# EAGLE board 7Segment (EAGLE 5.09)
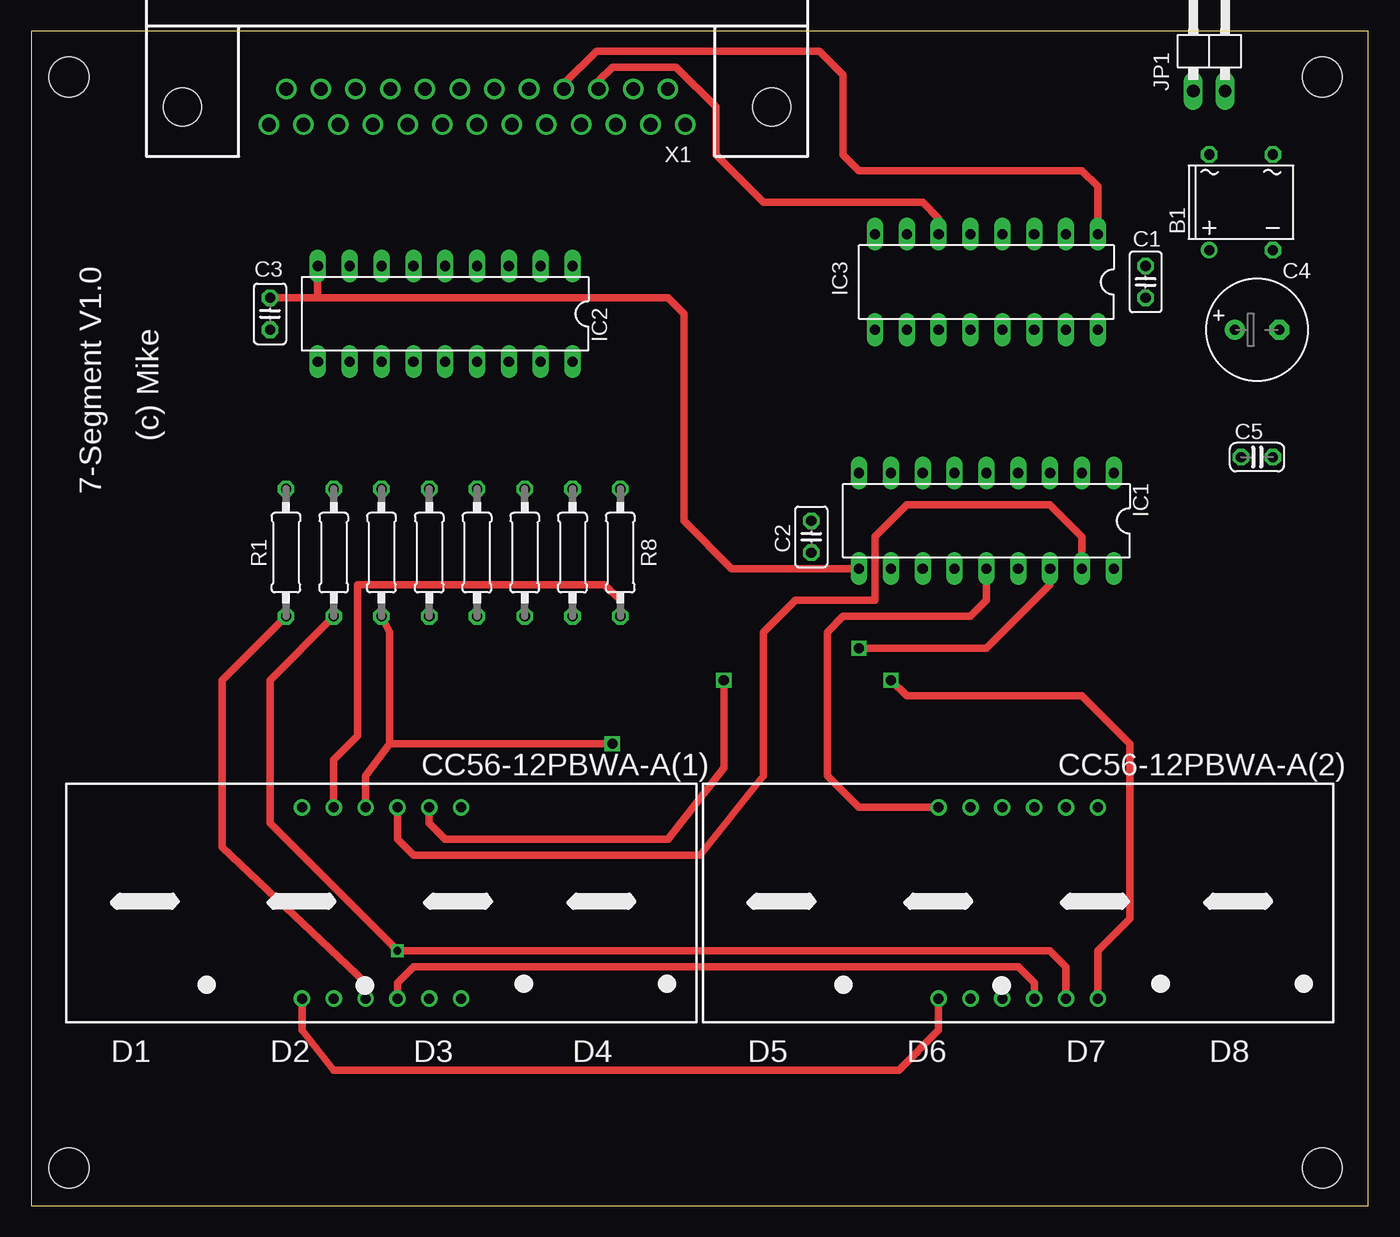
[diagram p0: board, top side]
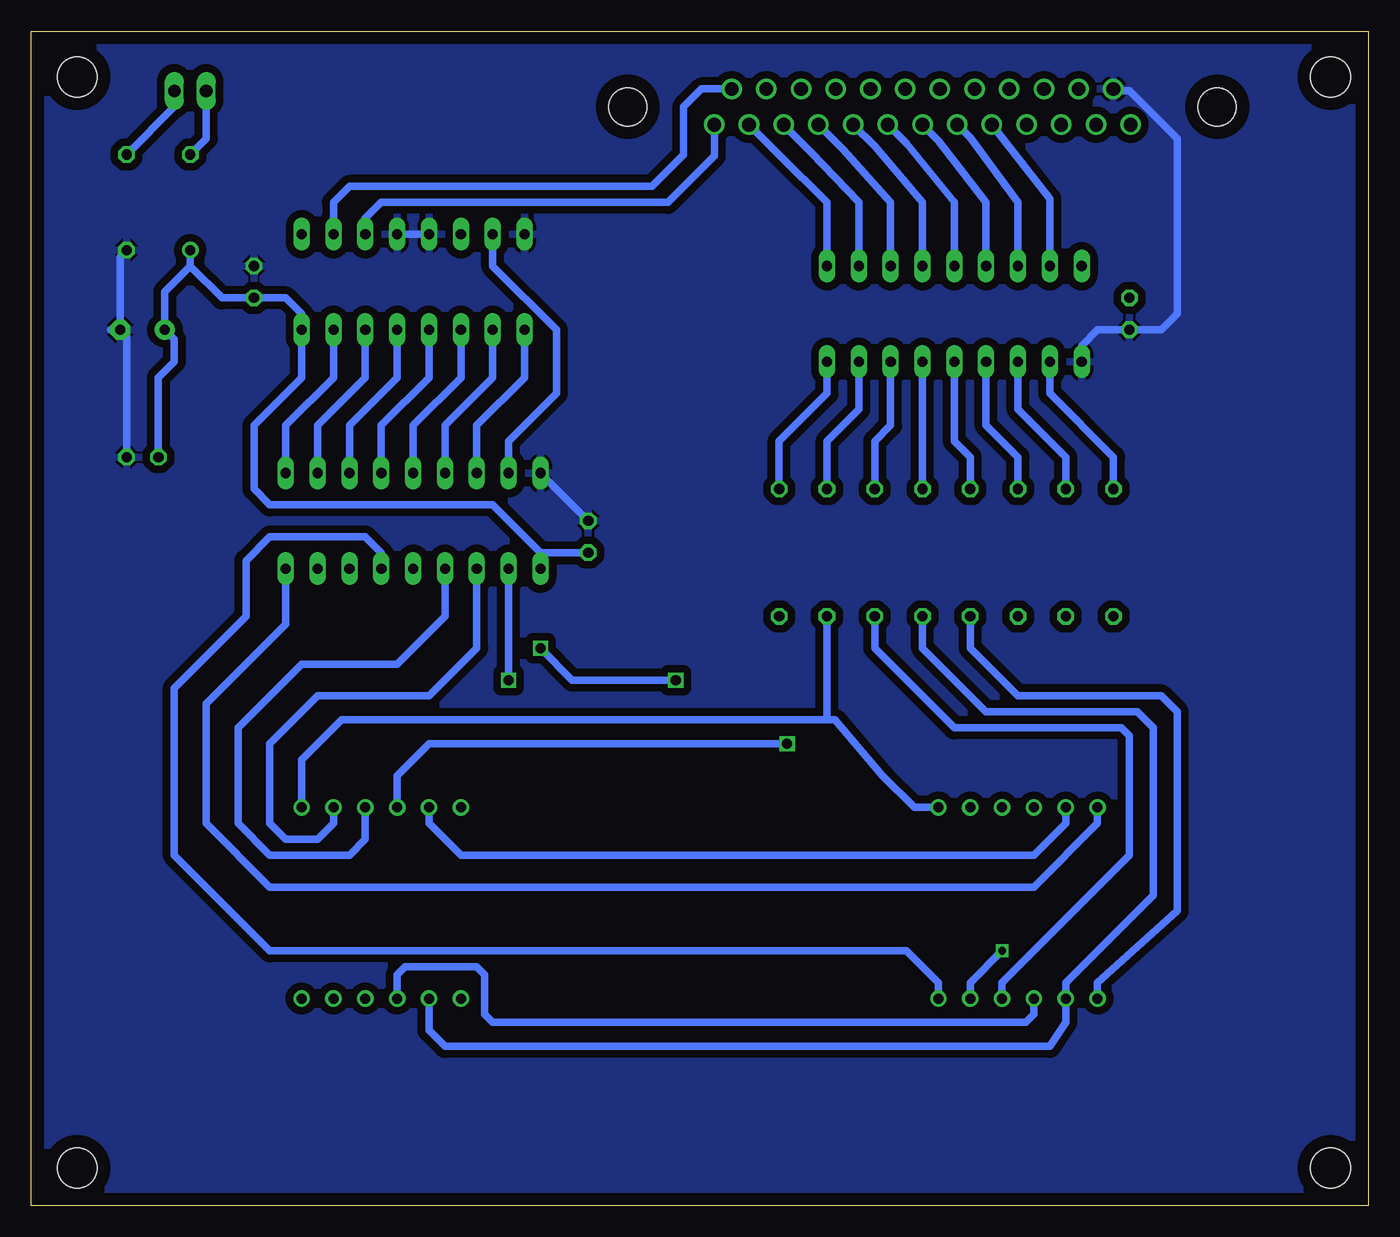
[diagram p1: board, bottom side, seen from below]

Size 106.66 x 93.65 mm. Coordinates in mm from the lower left corner, seen from the top.
Outline: 0,0 106.66,0 106.66,93.65 0,93.65 0,0
Copper layers (1*16): Top 0.035mm / dielectric 1.5mm / Bottom 0.035mm
Design rules "Bilex DRU": minimum track width 10mil, minimum drill 24mil, track to track 10mil, track to pad 10mil, pad to pad 10mil, via to via 10mil, smd to smd 10mil, copper to edge 40mil, drill to drill 8mil, minimum pad ring 10mil, minimum via ring 8mil, stop-mask expansion 4mil, vias tented up to drill 0mil, thermal gap 10mil
Holes 3.2 mm at 3,90 103,90 103,3 3,3

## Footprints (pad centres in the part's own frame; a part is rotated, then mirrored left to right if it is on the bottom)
DB = drill 0.813 round: + -2.54,-3.81 | drill 0.813 octagon: - 2.54,-3.81; AC1 2.54,3.81; AC2 -2.54,3.81
C025-025X050 = drill 0.813 octagon: 1 -1.27,0; 2 1.27,0
E3,5-8 = drill 0.813 pad 1.6 round: + -1.778,0 | drill 0.813 pad 1.6 octagon: - 1.778,0
C025-024X044 = drill 0.813 octagon: 1 -1.27,0; 2 1.27,0
4-FACH-7-SEG = drill 0.8 round: P1 -6.35,-7.62; P2 -3.81,-7.62; P3 -1.27,-7.62; P4 1.27,-7.62; P5 3.81,-7.62; P6 6.35,-7.62; P7 6.35,7.62; P8 3.81,7.62; P9 1.27,7.62; P10 -1.27,7.62; P11 -3.81,7.62; P12 -6.35,7.62
DIL18 = drill 0.813 long: 1 -10.16,-3.81; 2 -7.62,-3.81; 3 -5.08,-3.81; 4 -2.54,-3.81; 5 0,-3.81; 6 2.54,-3.81; 7 5.08,-3.81; 8 7.62,-3.81; 9 10.16,-3.81; 10 10.16,3.81; 11 7.62,3.81; 12 5.08,3.81; 13 2.54,3.81; 14 0,3.81; 15 -2.54,3.81; 16 -5.08,3.81; 17 -7.62,3.81; 18 -10.16,3.81
DIL16 = drill 0.813 long: 1 -8.89,-3.81; 2 -6.35,-3.81; 3 -3.81,-3.81; 4 -1.27,-3.81; 5 1.27,-3.81; 6 3.81,-3.81; 7 6.35,-3.81; 8 8.89,-3.81; 9 8.89,3.81; 10 6.35,3.81; 11 3.81,3.81; 12 1.27,3.81; 13 -1.27,3.81; 14 -3.81,3.81; 15 -6.35,3.81; 16 -8.89,3.81
1X02/90 = drill 1.016 long: 1 -1.27,-3.81; 2 1.27,-3.81
0207/10 = drill 0.813 octagon: 1 -5.08,0; 2 5.08,0
H3M25RA = drill 1.092 round: 1 -16.612,1.422; 2 -13.843,1.422; 3 -11.074,1.422; 4 -8.306,1.422; 5 -5.537,1.422; 6 -2.769,1.422; 7 0,1.422; 8 2.769,1.422; 9 5.537,1.422; 10 8.306,1.422; 11 11.074,1.422; 12 13.843,1.422; 13 16.612,1.422; 14 -15.227,-1.422; 15 -12.459,-1.422; 16 -9.69,-1.422; 17 -6.921,-1.422; 18 -4.153,-1.422; 19 -1.384,-1.422; 20 1.384,-1.422; 21 4.153,-1.422; 22 6.921,-1.422; 23 9.69,-1.422; 24 12.459,-1.422; 25 15.227,-1.422 | hole 3.048: -23.52,0; 23.52,0

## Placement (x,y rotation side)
B1  DBDB105G  [DB]  96.52,80.01 0 top
C1  100n  [C025-025X050]  88.9,73.66 270 top
C2  100n  [C025-025X050]  62.23,53.34 90 top
C3  100n  [C025-025X050]  19.05,71.12 90 top
C4  220u  [E3,5-8]  97.79,69.85 0 top
C5  100n  [C025-024X044]  97.79,59.69 0 top
CC56-12PBWA-A(1)  4-FACH-7-SEGCC56-12EWA  [4-FACH-7-SEG]  27.94,24.13 0 top
CC56-12PBWA-A(2)  4-FACH-7-SEGCC56-12EWA  [4-FACH-7-SEG]  78.74,24.13 0 top
IC1  ULN2803  [DIL18]  76.2,54.61 180 top
IC2  UDN2981A  [DIL18]  33.02,71.12 180 top
IC3  74237N  [DIL16]  76.2,73.66 180 top
JP1  [1X02/90]  93.98,92.71 0 top
R1  100  [0207/10]  20.32,52.07 90 top
R2  100  [0207/10]  24.13,52.07 90 top
R3  100  [0207/10]  27.94,52.07 90 top
R4  100  [0207/10]  31.75,52.07 90 top
R5  100  [0207/10]  35.56,52.07 90 top
R6  100  [0207/10]  39.37,52.07 90 top
R7  100  [0207/10]  43.18,52.07 90 top
R8  100  [0207/10]  46.99,52.07 90 top
X1  D-SUB25-H3M25RA  [H3M25RA]  35.56,87.63 180 top

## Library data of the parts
B1 = rectifier
C1-C5 R1-R8 = rcl
CC56-12PBWA-A(1) CC56-12PBWA-A(2) = MikeLib
IC1 IC2 = uln-udn
IC3 = 74ttl-din
JP1 = pinhead
X1 = con-thomas-betts

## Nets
+5V: B1.+ C1.2 C2.1 C3.2 C4.+ C5.1 IC1.10 IC2.9 IC3.16
GND: B1.- C1.1 C2.2 C3.1 C4.- C5.2 IC1.9 IC2.10 IC3.4 IC3.5 IC3.8 X1.25
N$1: IC2.11 R1.2
N$2: IC2.12 R2.2
N$3: IC2.13 R3.2
N$4: IC2.14 R4.2
N$5: IC2.15 R5.2
N$6: IC2.16 R6.2
N$7: IC2.17 R7.2
N$8: IC2.18 R8.2
N$9: IC1.1 IC3.15
N$10: IC1.2 IC3.14
N$11: IC1.3 IC3.13
N$12: IC1.4 IC3.12
N$13: IC1.5 IC3.11
N$14: IC1.6 IC3.10
N$15: IC1.7 IC3.9
N$16: IC1.8 IC3.7
N$17: CC56-12PBWA-A(1).P3 CC56-12PBWA-A(2).P3 R1.1
N$18: CC56-12PBWA-A(1).P5 CC56-12PBWA-A(2).P5 R2.1
N$19: CC56-12PBWA-A(1).P10 CC56-12PBWA-A(2).P10 R3.1
N$20: CC56-12PBWA-A(1).P1 CC56-12PBWA-A(2).P1 R4.1
N$21: CC56-12PBWA-A(1).P2 CC56-12PBWA-A(2).P2 R5.1
N$22: CC56-12PBWA-A(1).P4 CC56-12PBWA-A(2).P4 R6.1
N$23: CC56-12PBWA-A(1).P7 CC56-12PBWA-A(2).P7 R7.1
N$24: CC56-12PBWA-A(1).P11 CC56-12PBWA-A(2).P11 R8.1
N$25: CC56-12PBWA-A(2).P6 IC1.11
N$26: CC56-12PBWA-A(2).P8 IC1.12
N$27: CC56-12PBWA-A(2).P9 IC1.13
N$28: CC56-12PBWA-A(2).P12 IC1.14
N$29: CC56-12PBWA-A(1).P12 IC1.18
N$30: CC56-12PBWA-A(1).P6 IC1.15
N$31: CC56-12PBWA-A(1).P8 IC1.16
N$32: CC56-12PBWA-A(1).P9 IC1.17
N$33: IC2.8 X1.9
N$34: B1.AC1 JP1.2
N$35: IC2.7 X1.8
N$36: IC2.6 X1.7
N$37: IC2.5 X1.6
N$38: IC2.4 X1.5
N$39: IC2.3 X1.4
N$40: IC2.2 X1.3
N$41: IC2.1 X1.2
N$42: B1.AC2 JP1.1
SUB25-D1: IC3.3 X1.1
SUB25-D14: IC3.2 X1.14
SUB25-D16: IC3.6 X1.16
SUB25-D17: IC3.1 X1.17

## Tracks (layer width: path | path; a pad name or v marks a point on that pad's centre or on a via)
+5V
  Top 0.61: C3.2 22.86,72.39 | 22.86,72.39 IC2.9 | 22.86,72.39 50.8,72.39 52.07,71.12 52.07,54.61 55.88,50.8 IC1.10
  Bottom 0.6: C2.1 66.04,52.07 IC1.10 | C1.2 86.36,72.39 85.09,71.12 IC3.16
  Bottom 0.61: 66.04,52.07 69.85,55.88 87.63,55.88 88.9,57.15 88.9,62.23 85.09,66.04 IC3.16 | 93.98,74.93 91.44,72.39 C1.2 | 93.98,74.93 B1.+ | 93.98,74.93 96.01,72.9 C4.+ 95.25,69.09 95.25,67.31 96.52,66.04 C5.1
GND
  Bottom 0.6: C2.2 IC1.9 | IC3.5 IC3.4
  Bottom 0.61: IC2.10 22.86,68.58 21.59,69.85 C3.1 16.51,69.85 15.24,71.12 15.24,85.09 19.05,88.9 20.18,88.9 X1.25 | C5.2 99.06,69.85 C4.- | C4.- 100.33,69.85 | C4.- 99.57,75.69 B1.-
  pour Bottom (isolate 0.61): -7.62,97.79 113.03,97.79 113.03,93.98 114.3,93.98 114.3,-6.35 -6.35,-6.35 -6.35,-5.08 -7.62,-5.08
N$1
  Bottom 0.6: IC2.11 25.4,64.77 20.32,59.69 R1.2
N$2
  Bottom 0.6: IC2.12 27.94,63.5 24.13,59.69 R2.2
N$3
  Bottom 0.6: IC2.13 30.48,62.23 27.94,59.69 R3.2
N$4
  Bottom 0.6: IC2.14 33.02,60.96 31.75,59.69 R4.2
N$5
  Bottom 0.6: R5.2 IC2.15
N$6
  Bottom 0.6: IC2.16 38.1,62.23 39.37,60.96 R6.2
N$7
  Bottom 0.6: IC2.17 40.64,63.5 43.18,60.96 R7.2
N$8
  Bottom 0.6: IC2.18 43.18,64.77 46.99,60.96 R8.2
N$9
  Bottom 0.6: IC3.15 82.55,66.04 86.36,62.23 IC1.1
N$10
  Bottom 0.6: IC3.14 80.01,66.04 83.82,62.23 IC1.2
N$11
  Bottom 0.6: IC3.13 77.47,66.04 81.28,62.23 IC1.3
N$12
  Bottom 0.6: IC3.12 74.93,66.04 78.74,62.23 IC1.4
N$13
  Bottom 0.6: IC3.11 72.39,66.04 76.2,62.23 IC1.5
N$14
  Bottom 0.6: IC3.10 69.85,66.04 73.66,62.23 IC1.6
N$15
  Bottom 0.6: IC3.9 67.31,66.04 71.12,62.23 IC1.7
N$16
  Bottom 0.61: IC1.8 68.58,60.96 64.77,64.77 64.77,69.85 69.85,74.93 IC3.7
N$17
  Top 0.61: CC56-12PBWA-A(1).P3 26.67,17.78 15.24,28.57 15.24,41.91 R1.1
  Bottom 0.61: CC56-12PBWA-A(1).P3 26.67,15.24 27.3,14.61 69.85,14.61 70.48,15.24 70.48,15.88 70.48,18.41 71.12,19.05 76.83,19.05 77.47,18.41 CC56-12PBWA-A(2).P3
N$18  (via drill 0.6)
  Top 0.61: R2.1 19.05,41.91 19.05,30.48 v29.21,20.32 81.28,20.32 82.55,19.05 CC56-12PBWA-A(2).P5
  Bottom 0.61: CC56-12PBWA-A(1).P5 31.75,17.78 v29.21,20.32
N$19  (via drill 0.8)
  Top 0.61: R3.1 28.57,45.72 28.57,36.83 | CC56-12PBWA-A(1).P10 26.67,34.29 28.57,36.83 | 28.57,36.83 v46.35,36.83
  Bottom 0.61: CC56-12PBWA-A(2).P10 77.47,34.29 74.93,36.83 v46.35,36.83
N$20
  Top 0.61: CC56-12PBWA-A(2).P1 72.39,13.97 69.22,10.79 24.13,10.79 21.59,13.97 CC56-12PBWA-A(1).P1
  Bottom 0.61: CC56-12PBWA-A(1).P1 21.59,17.78 15.24,23.5 15.24,39.37 16.51,40.64 27.94,40.64 31.75,44.45 R4.1
N$21
  Bottom 0.61: CC56-12PBWA-A(2).P2 74.93,13.97 73.66,12.7 25.4,12.7 24.13,14.61 CC56-12PBWA-A(1).P2 24.13,17.78 17.14,24.77 17.14,38.1 18.41,39.37 30.48,39.37 35.56,44.45 R5.1
N$22
  Top 0.61: CC56-12PBWA-A(2).P4 80.01,17.78 78.74,19.05 30.48,19.05 29.21,17.78 CC56-12PBWA-A(1).P4
  Bottom 0.61: CC56-12PBWA-A(1).P4 29.21,17.78 19.05,27.94 19.05,37.47 19.68,38.1 33.02,38.1 39.37,44.45 R6.1
N$23
  Bottom 0.61: CC56-12PBWA-A(2).P7 85.09,35.56 81.92,38.73 43.18,38.73 | CC56-12PBWA-A(1).P7 36.2,31.75 38.73,34.29 42.55,38.73 43.18,38.73 | 43.18,38.73 R7.1
N$24
  Top 0.61: R8.1 46.99,48.26 45.72,49.53 26.04,49.53 26.04,37.47 24.13,35.56 CC56-12PBWA-A(1).P11
  Bottom 0.61: CC56-12PBWA-A(2).P11 74.93,30.48 72.39,27.94 26.67,27.94 24.13,30.48 CC56-12PBWA-A(1).P11
N$25  (via drill 0.8)
  Top 0.61: v68.58,41.91 69.85,40.64 83.82,40.64 87.63,36.83 87.63,22.86 85.09,20.32 CC56-12PBWA-A(2).P6
  Bottom 0.61: v68.58,41.91 IC1.11
N$26
  Bottom 0.61: CC56-12PBWA-A(2).P8 82.55,30.48 83.82,29.21 86.36,29.21 87.63,30.48 87.63,36.83 83.82,40.64 74.93,40.64 71.12,44.45 IC1.12
N$27
  Bottom 0.61: CC56-12PBWA-A(2).P9 80.01,29.21 81.28,27.94 87.63,27.94 90.17,30.48 90.17,38.1 85.09,43.18 77.47,43.18 73.66,46.99 IC1.13
N$28
  Top 0.61: CC56-12PBWA-A(2).P12 66.04,31.75 63.5,34.29 63.5,45.72 64.77,46.99 74.93,46.99 76.2,48.26 IC1.14
N$29
  Bottom 0.61: CC56-12PBWA-A(1).P12 21.59,30.48 26.67,25.4 87.63,25.4 92.71,30.48 92.71,40.01 87.63,45.09 86.36,46.35 IC1.18
N$30
  Bottom 0.61: CC56-12PBWA-A(1).P6 34.29,17.78 36.83,20.32 87.63,20.32 95.25,27.94 95.25,41.27 89.53,46.99 89.53,51.44 87.63,53.34 80.01,53.34 78.74,52.07 IC1.15
N$31  (via drill 0.8)
  Top 0.61: v66.04,44.45 76.2,44.45 81.28,49.53 IC1.16 | v55.24,41.91 55.24,34.92 50.8,29.21 33.02,29.21 31.75,30.48 CC56-12PBWA-A(1).P8
  Bottom 0.61: v55.24,41.91 63.5,41.91 v66.04,44.45
N$32
  Top 0.61: CC56-12PBWA-A(1).P9 29.21,29.84 29.21,29.21 30.48,27.94 53.34,27.94 58.42,34.29 58.42,45.72 60.96,48.26 67.31,48.26 67.31,53.34 69.85,55.88 81.28,55.88 83.82,53.34 IC1.17
N$33
  Bottom 0.61: IC2.8 25.4,80.31 X1.9
N$34
  Bottom 0.61: JP1.2 95.25,87.63 B1.AC1
N$35
  Bottom 0.61: IC2.7 27.94,80.01 31.75,85.17 X1.8
N$36
  Bottom 0.61: IC2.6 30.48,80.01 34.29,84.94 X1.7
N$37
  Bottom 0.61: IC2.5 33.02,80.01 36.83,84.71 X1.6
N$38
  Bottom 0.61: IC2.4 35.56,80.01 39.37,84.48 X1.5
N$39
  Bottom 0.61: IC2.3 38.1,80.01 41.91,84.25 X1.4
N$40
  Bottom 0.61: IC2.2 40.64,80.01 44.45,84.02 X1.3
N$41
  Bottom 0.61: IC2.1 43.18,80.01 46.99,83.82 47.02,83.82 X1.2
N$42
  Bottom 0.61: JP1.1 92.71,85.09 B1.AC2
SUB25-D1
  Bottom 0.61: X1.1 52.17,83.72 55.88,80.01 78.74,80.01 80.01,78.74 IC3.3
SUB25-D14
  Bottom 0.61: X1.14 53.19,89.05 54.61,87.63 54.61,83.82 57.15,81.28 81.28,81.28 82.55,80.01 IC3.2
SUB25-D16
  Top 0.61: X1.16 45.25,89.7 46.35,90.81 51.44,90.81 54.61,87.63 54.61,83.82 58.42,80.01 71.12,80.01 72.39,78.74 IC3.6
SUB25-D17
  Top 0.61: X1.17 42.48,89.47 45.09,92.08 62.87,92.08 64.77,90.17 64.77,83.82 66.04,82.55 83.82,82.55 85.09,81.28 IC3.1

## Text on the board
tNames: 7-Segment V1.0 | (c) Mike | D1 | D2 | D3 | D4 | D5 | D6 | D7 | D8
